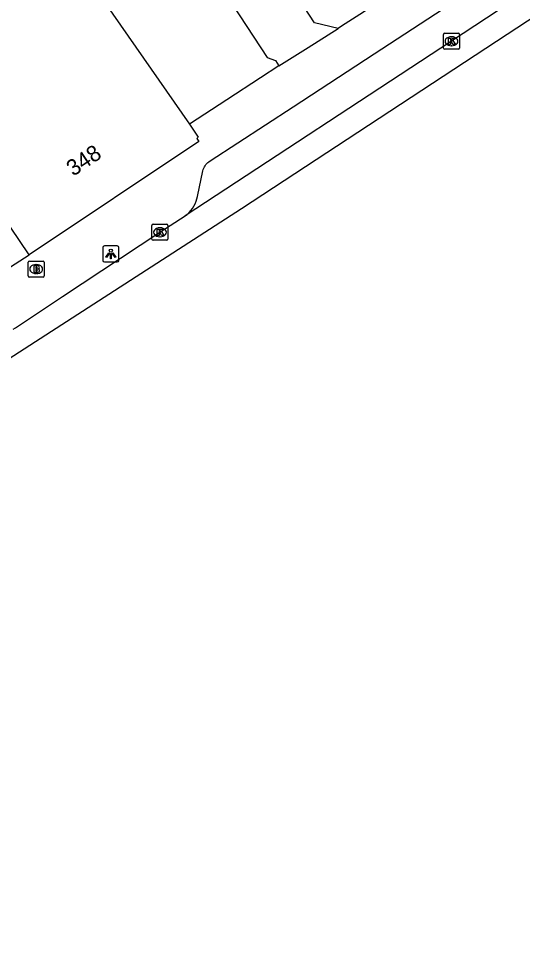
# Model space of a CAD drawing. Extents: x 159222 to 160346, y 381249 to 382166.
# Drawn here: x 160060.5 to 160092, y 381528.6 to 381586.7 of the extents above; entities that cross this region are included whole.
import ezdxf

# ---------------------------------------------------------------- set-up
doc = ezdxf.new("R2010")
doc.units = 0
for name, color, linetype in [('IMGEO_Brandkraan', 7, 'Continuous'), ('IMGEO_Kolk', 7, 'Continuous'), ('IMGEO_Lichtpunt', 7, 'Continuous'), ('IMGEO_Pand', 7, 'Continuous'), ('IMGEO_Pand_nummerreeks', 7, 'Continuous'), ('IMGEO_Pand_overbouw', 7, 'Continuous'), ('IMGEO_Rijbaan_lokaal_gesloten', 7, 'Continuous'), ('IMGEO_Voetpad_open', 7, 'Continuous')]:
    doc.layers.add(name, color=color, linetype=linetype)

msp = doc.modelspace()

# ---------------------------------------------------------------- linework, layer by layer
at = {"layer": 'IMGEO_Brandkraan'}
for p, q in [((160061.14, 381570.594), (160061.14, 381571.446)), ((160061.215, 381571.52), (160062.067, 381571.52)), ((160061.628, 381571.3), (160061.653, 381571.3)), ((160062.141, 381571.446), (160062.141, 381570.594)), ((160061.651, 381570.74), (160061.626, 381570.74)), ((160062.067, 381570.52), (160061.215, 381570.52))]:
    msp.add_line(p, q, dxfattribs=at)
for points in [[(160061.14, 381570.594), (160061.14, 381571.446)], [(160061.215, 381571.52), (160062.067, 381571.52)], [(160061.488, 381571.22), (160061.488, 381570.82), (160061.701, 381570.82)], [(160061.719, 381571.22), (160061.488, 381571.22)], [(160061.667, 381571.139), (160061.613, 381571.139), (160061.613, 381571.063)], [(160062.141, 381571.446), (160062.141, 381570.594)], [(160061.613, 381571.063), (160061.666, 381571.063)], [(160061.675, 381570.987), (160061.613, 381570.987), (160061.613, 381570.906)], [(160061.613, 381570.906), (160061.675, 381570.906)], [(160062.067, 381570.52), (160061.215, 381570.52)]]:
    msp.add_lwpolyline(points, dxfattribs=at)
for centre, radius, start, end in [((160061.217, 381571.444), 0.0765, 91.55205, 178.44795), ((160061.217, 381571.444), 0.0765, 91.55205, 178.44795), ((160061.668, 381571.101), 0.0379, 267.82845, 90.93552), ((160061.723, 381571.075), 0.145, 59.4692, 91.53667), ((160061.748, 381571.122), 0.0922, 285.51372, 58.15012), ((160062.065, 381571.444), 0.0765, 1.55205, 88.44795), ((160062.065, 381571.444), 0.0765, 1.55205, 88.44795), ((160061.217, 381570.596), 0.0765, 181.55205, 268.44795), ((160061.217, 381570.596), 0.0765, 181.55205, 268.44795), ((160061.676, 381570.946), 0.0404, 269.87594, 90.50774), ((160061.707, 381571.071), 0.251, 268.66757, 293.53466), ((160061.753, 381570.93), 0.105, 301.31148, 78.98903), ((160062.065, 381570.596), 0.0765, 271.55205, 358.44795), ((160062.065, 381570.596), 0.0765, 271.55205, 358.44795)]:
    msp.add_arc(centre, radius, start, end, dxfattribs=at)
for centre, major_axis, ratio, start_param, end_param in [((160061.627, 381571.02), (-0.387, 0.002), 0.722429, 4.712389, 7.853982), ((160061.652, 381571.02), (-0.39, 0.002), 0.717154, 1.570796, 4.712389)]:
    msp.add_ellipse(centre, major_axis=major_axis, ratio=ratio, start_param=start_param, end_param=end_param, dxfattribs=at)
at = {"layer": 'IMGEO_Kolk'}
for p, q in [((160087.082, 381584.827), (160087.082, 381585.679)), ((160087.157, 381585.753), (160088.009, 381585.753)), ((160088.083, 381585.679), (160088.083, 381584.827)), ((160087.57, 381585.533), (160087.595, 381585.533)), ((160088.009, 381584.753), (160087.157, 381584.753)), ((160087.593, 381584.973), (160087.568, 381584.973)), ((160068.87, 381572.894), (160068.87, 381573.746)), ((160068.945, 381573.82), (160069.797, 381573.82)), ((160069.358, 381573.6), (160069.383, 381573.6)), ((160069.871, 381573.746), (160069.871, 381572.894)), ((160069.381, 381573.04), (160069.356, 381573.04)), ((160069.797, 381572.82), (160068.945, 381572.82))]:
    msp.add_line(p, q, dxfattribs=at)
for points in [[(160087.082, 381584.827), (160087.082, 381585.679)], [(160087.157, 381585.753), (160088.009, 381585.753)], [(160088.083, 381585.679), (160088.083, 381584.827)], [(160087.403, 381585.453), (160087.526, 381585.453), (160087.526, 381585.302), (160087.656, 381585.453), (160087.82, 381585.453), (160087.674, 381585.302), (160087.827, 381585.053), (160087.675, 381585.053), (160087.59, 381585.217), (160087.526, 381585.15), (160087.526, 381585.053), (160087.403, 381585.053), (160087.403, 381585.453)], [(160088.009, 381584.753), (160087.157, 381584.753)], [(160068.87, 381572.894), (160068.87, 381573.746)], [(160068.945, 381573.82), (160069.797, 381573.82)], [(160069.191, 381573.52), (160069.314, 381573.52), (160069.314, 381573.369), (160069.444, 381573.52), (160069.608, 381573.52), (160069.462, 381573.369), (160069.615, 381573.12), (160069.463, 381573.12), (160069.378, 381573.284), (160069.314, 381573.217), (160069.314, 381573.12), (160069.191, 381573.12), (160069.191, 381573.52)], [(160069.871, 381573.746), (160069.871, 381572.894)], [(160069.797, 381572.82), (160068.945, 381572.82)]]:
    msp.add_lwpolyline(points, dxfattribs=at)
for centre, start, end in [((160087.159, 381585.677), 91.55205, 178.44795), ((160087.159, 381585.677), 91.55205, 178.44795), ((160088.007, 381585.677), 1.55205, 88.44795), ((160088.007, 381585.677), 1.55205, 88.44795), ((160087.159, 381584.829), 181.55205, 268.44795), ((160087.159, 381584.829), 181.55205, 268.44795), ((160088.007, 381584.829), 271.55205, 358.44795), ((160088.007, 381584.829), 271.55205, 358.44795), ((160068.947, 381573.744), 91.55205, 178.44795), ((160068.947, 381573.744), 91.55205, 178.44795), ((160069.795, 381573.744), 1.55205, 88.44795), ((160069.795, 381573.744), 1.55205, 88.44795), ((160068.947, 381572.896), 181.55205, 268.44795), ((160068.947, 381572.896), 181.55205, 268.44795), ((160069.795, 381572.896), 271.55205, 358.44795), ((160069.795, 381572.896), 271.55205, 358.44795)]:
    msp.add_arc(centre, 0.0765, start, end, dxfattribs=at)
for centre, major_axis, ratio, start_param, end_param in [((160087.569, 381585.253), (-0.387, 0.002), 0.722429, 4.712389, 7.853982), ((160087.594, 381585.253), (-0.39, 0.002), 0.717154, 1.570796, 4.712389), ((160069.357, 381573.32), (-0.387, 0.002), 0.722429, 4.712389, 7.853982), ((160069.382, 381573.32), (-0.39, 0.002), 0.717154, 1.570796, 4.712389)]:
    msp.add_ellipse(centre, major_axis=major_axis, ratio=ratio, start_param=start_param, end_param=end_param, dxfattribs=at)
at = {"layer": 'IMGEO_Lichtpunt'}
for p, q in [((160065.803, 381572.375), (160065.803, 381571.568)), ((160065.803, 381572.375), (160065.803, 381571.568)), ((160066.705, 381572.47), (160065.897, 381572.47)), ((160066.705, 381572.47), (160065.897, 381572.47)), ((160066.799, 381571.568), (160066.799, 381572.375)), ((160066.799, 381571.568), (160066.799, 381572.375)), ((160065.897, 381571.474), (160066.705, 381571.474)), ((160065.897, 381571.474), (160066.705, 381571.474))]:
    msp.add_line(p, q, dxfattribs=at)
for points in [[(160066.177, 381572.039), (160066.216, 381572.011), (160066.028, 381571.749), (160065.99, 381571.776), (160066.177, 381572.039)], [(160066.279, 381571.991), (160066.326, 381571.991), (160066.326, 381571.669), (160066.279, 381571.669), (160066.279, 381571.991)], [(160066.389, 381572.011), (160066.427, 381572.038), (160066.614, 381571.776), (160066.575, 381571.748), (160066.389, 381572.011)]]:
    msp.add_lwpolyline(points, dxfattribs=at)
msp.add_circle((160066.302, 381572.173), 0.0994, dxfattribs=at)
for centre, start, end in [((160065.897, 381572.375), 90, 180), ((160065.897, 381572.375), 90, 180), ((160066.705, 381572.375), 0, 90), ((160066.705, 381572.375), 0, 90), ((160065.897, 381571.568), 180, 270), ((160065.897, 381571.568), 180, 270), ((160066.705, 381571.568), 270, 0), ((160066.705, 381571.568), 270, 360)]:
    msp.add_arc(centre, 0.0946, start, end, dxfattribs=at)
at = {"layer": 'IMGEO_Pand'}
for points in [[(160080.507, 381586.051), (160079.028, 381586.399), (160074.124, 381593.909), (160073.116, 381594.445), (160072.253, 381595.767), (160070.382, 381598.632), (160066.385, 381604.751), (160074.71, 381610.148), (160078.905, 381612.867)], [(160064.034, 381590.405), (160065.441, 381591.324), (160069.627, 381594.058), (160076.071, 381584.244), (160076.584, 381584.042), (160076.802, 381583.707)], [(160091.81, 381593.432), (160088.964, 381591.573), (160086.871, 381590.207), (160083.94, 381588.293), (160081.847, 381586.926), (160080.717, 381586.188), (160080.507, 381586.051)], [(160064.034, 381590.405), (160071.216, 381580.08)], [(160076.802, 381583.707), (160075.656, 381582.963), (160073.55, 381581.596), (160071.216, 381580.08)], [(160071.216, 381580.08), (160071.758, 381579.255), (160071.673, 381579.183), (160071.796, 381578.997), (160061.199, 381571.915)], [(160061.199, 381571.915), (160058.326, 381576.141)]]:
    msp.add_lwpolyline(points, dxfattribs=at)
at = {"layer": 'IMGEO_Pand_overbouw'}
msp.add_lwpolyline([(160069.627, 381594.058), (160076.071, 381584.244), (160076.584, 381584.042), (160076.802, 381583.707), (160078.623, 381584.859), (160080.507, 381586.051), (160079.028, 381586.399), (160074.124, 381593.909), (160073.116, 381594.445), (160072.253, 381595.767)], close=True, dxfattribs=at)
at = {"layer": 'IMGEO_Rijbaan_lokaal_gesloten'}
for points in [[(160138.741, 381619.241), (160139.591, 381617.866), (160137.265, 381616.308), (160135.358, 381615.03), (160108.254, 381596.98), (160074.47, 381574.782), (160035.773, 381549.819), (160006.52, 381531.153), (160002.266, 381528.592)], [(160134.606, 381616.433), (160131.298, 381614.262), (160103.074, 381595.46), (160087.579, 381585.252), (160070.937, 381574.339)], [(160060.2, 381567.27), (160060.34, 381567.361), (160063.293, 381569.303), (160069.367, 381573.319), (160070.937, 381574.339)]]:
    msp.add_lwpolyline(points, dxfattribs=at)
at = {"layer": 'IMGEO_Voetpad_open'}
for points in [[(160070.937, 381574.339), (160071.07, 381574.44), (160071.192, 381574.553), (160071.305, 381574.677), (160071.406, 381574.81), (160071.494, 381574.951), (160071.57, 381575.1), (160071.632, 381575.255), (160071.68, 381575.415), (160071.708, 381575.547), (160072.053, 381577.155), (160072.055, 381577.166), (160072.079, 381577.249), (160072.109, 381577.329), (160072.147, 381577.406), (160072.192, 381577.48), (160072.242, 381577.55), (160072.299, 381577.614), (160072.362, 381577.673), (160072.429, 381577.727), (160072.501, 381577.774), (160077.685, 381581.161), (160082.741, 381584.465), (160091.857, 381590.422)], [(160076.802, 381583.707), (160078.623, 381584.859), (160080.507, 381586.051)], [(159997.825, 381531.064), (159997.877, 381531.093), (160000, 381532.468), (160024.711, 381548.473), (160061.199, 381571.915)]]:
    msp.add_lwpolyline(points, dxfattribs=at)

# ---------------------------------------------------------------- texts
at = {"layer": 'IMGEO_Pand_nummerreeks'}
msp.add_text('348', height=1, rotation=33.7549, dxfattribs=at).set_placement((160063.954, 381576.787))

doc.saveas('drawing.dxf')
